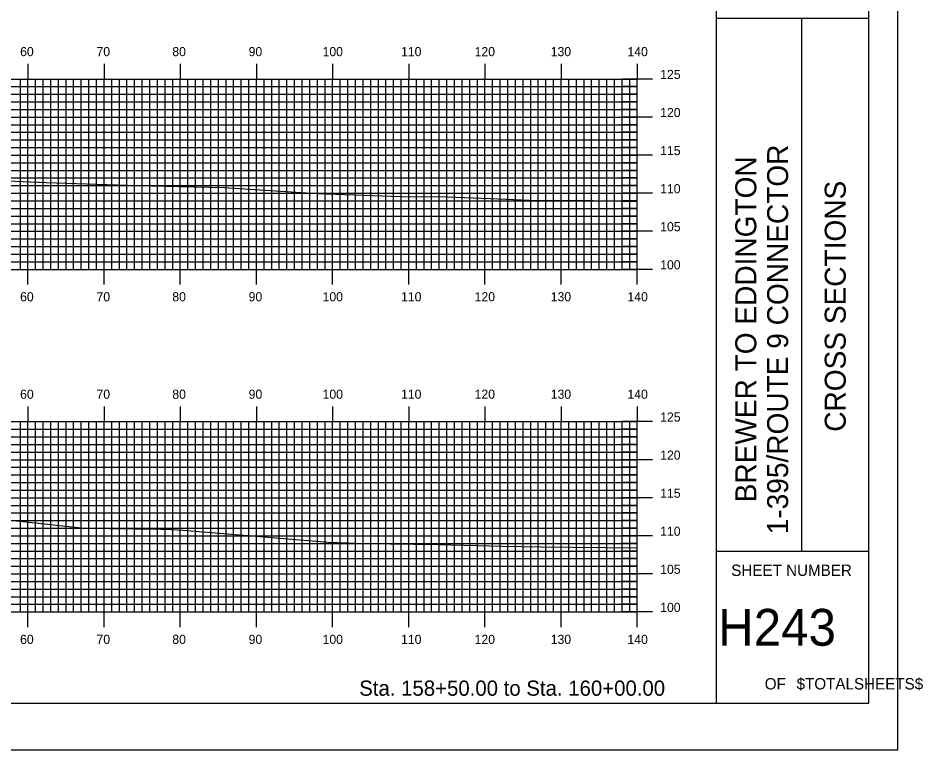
# Model space of a CAD drawing. Extents: x 1779893 to 1780236, y 442591 to 442811.
# Drawn here: x 1780117.1 to 1780235.9, y 442590.5 to 442686.7 of the extents above; entities that cross this region are included whole.
import ezdxf

# ---------------------------------------------------------------- set-up
doc = ezdxf.new("R2010")
doc.units = 0
for name, color, linetype in [('BORDER', 7, 'Continuous'), ('H_V ANNOTATION', 7, 'Continuous'), ('MAJOR', 7, 'Continuous'), ('MINOR', 7, 'Continuous'), ('PLOT BOUNDARY', 7, 'Continuous'), ('S_Roadway_Centerline', 7, 'Continuous')]:
    doc.layers.add(name, color=color, linetype=linetype)

msp = doc.modelspace()

# ---------------------------------------------------------------- linework, layer by layer
at = {"layer": 'BORDER'}
for p, q in [((1780208.76, 442596.67), (1780208.76, 442806.67)), ((1780208.76, 442686.67), (1780228.76, 442686.67)), ((1780219.94, 442616.67), (1780219.94, 442686.67)), ((1780208.76, 442616.67), (1780228.76, 442616.67))]:
    msp.add_line(p, q, dxfattribs=at)
msp.add_lwpolyline([(1779908.76, 442596.67), (1780228.76, 442596.67), (1780228.76, 442806.67), (1779908.76, 442806.67)], close=True, dxfattribs=at)
at = {"layer": 'MAJOR'}
for p, q in [((1780118.36, 442680.67), (1780118.36, 442678.67)), ((1780128.36, 442680.67), (1780128.36, 442678.67)), ((1780138.36, 442680.67), (1780138.36, 442678.67)), ((1780148.36, 442680.67), (1780148.36, 442678.67)), ((1780158.36, 442680.67), (1780158.36, 442678.67)), ((1780168.36, 442680.67), (1780168.36, 442678.67)), ((1780178.36, 442680.67), (1780178.36, 442678.67)), ((1780188.36, 442680.67), (1780188.36, 442678.67)), ((1780198.36, 442680.67), (1780198.36, 442678.67)), ((1779918.36, 442678.67), (1780198.36, 442678.67)), ((1779918.36, 442678.67), (1780198.36, 442678.67)), ((1780118.36, 442653.67), (1780118.36, 442678.67)), ((1780128.36, 442653.67), (1780128.36, 442678.67)), ((1780138.36, 442653.67), (1780138.36, 442678.67)), ((1780148.36, 442653.67), (1780148.36, 442678.67)), ((1780158.36, 442653.67), (1780158.36, 442678.67)), ((1780168.36, 442653.67), (1780168.36, 442678.67)), ((1780178.36, 442653.67), (1780178.36, 442678.67)), ((1780188.36, 442653.67), (1780188.36, 442678.67)), ((1780200.36, 442678.67), (1780196.35, 442678.67)), ((1780198.36, 442653.67), (1780198.36, 442678.67)), ((1780198.36, 442653.67), (1780198.36, 442678.67)), ((1779918.36, 442673.67), (1780198.36, 442673.67)), ((1780200.36, 442673.67), (1780196.35, 442673.67)), ((1779918.36, 442668.67), (1780198.36, 442668.67)), ((1780200.36, 442668.67), (1780196.35, 442668.67)), ((1779918.36, 442663.67), (1780198.36, 442663.67)), ((1780200.36, 442663.67), (1780196.35, 442663.67)), ((1779918.36, 442658.67), (1780198.36, 442658.67)), ((1780200.36, 442658.67), (1780196.35, 442658.67)), ((1779918.36, 442653.67), (1780198.36, 442653.67)), ((1779918.36, 442653.67), (1780198.36, 442653.67)), ((1780118.36, 442651.66), (1780118.36, 442653.67)), ((1780128.36, 442651.66), (1780128.36, 442653.67)), ((1780138.36, 442651.66), (1780138.36, 442653.67)), ((1780148.36, 442651.66), (1780148.36, 442653.67)), ((1780158.36, 442651.66), (1780158.36, 442653.67)), ((1780168.36, 442651.66), (1780168.36, 442653.67)), ((1780178.36, 442651.66), (1780178.36, 442653.67)), ((1780188.36, 442651.66), (1780188.36, 442653.67)), ((1780200.36, 442653.67), (1780196.35, 442653.67)), ((1780198.36, 442651.66), (1780198.36, 442653.67)), ((1780118.36, 442635.67), (1780118.36, 442633.67)), ((1780128.36, 442635.67), (1780128.36, 442633.67)), ((1780138.36, 442635.67), (1780138.36, 442633.67)), ((1780148.36, 442635.67), (1780148.36, 442633.67)), ((1780158.36, 442635.67), (1780158.36, 442633.67)), ((1780168.36, 442635.67), (1780168.36, 442633.67)), ((1780178.36, 442635.67), (1780178.36, 442633.67)), ((1780188.36, 442635.67), (1780188.36, 442633.67)), ((1780198.36, 442635.67), (1780198.36, 442633.67)), ((1779918.36, 442633.67), (1780198.36, 442633.67)), ((1779918.36, 442633.67), (1780198.36, 442633.67)), ((1780118.36, 442608.67), (1780118.36, 442633.67)), ((1780128.36, 442608.67), (1780128.36, 442633.67)), ((1780138.36, 442608.67), (1780138.36, 442633.67)), ((1780148.36, 442608.67), (1780148.36, 442633.67)), ((1780158.36, 442608.67), (1780158.36, 442633.67)), ((1780168.36, 442608.67), (1780168.36, 442633.67)), ((1780178.36, 442608.67), (1780178.36, 442633.67)), ((1780188.36, 442608.67), (1780188.36, 442633.67)), ((1780200.36, 442633.67), (1780196.35, 442633.67)), ((1780198.36, 442608.67), (1780198.36, 442633.67)), ((1780198.36, 442608.67), (1780198.36, 442633.67)), ((1779918.36, 442628.67), (1780198.36, 442628.67)), ((1780200.36, 442628.67), (1780196.35, 442628.67)), ((1779918.36, 442623.67), (1780198.36, 442623.67)), ((1780200.36, 442623.67), (1780196.35, 442623.67)), ((1779918.36, 442618.67), (1780198.36, 442618.67)), ((1780200.36, 442618.67), (1780196.35, 442618.67)), ((1779918.36, 442613.67), (1780198.36, 442613.67)), ((1780200.36, 442613.67), (1780196.35, 442613.67)), ((1779918.36, 442608.67), (1780198.36, 442608.67)), ((1779918.36, 442608.67), (1780198.36, 442608.67)), ((1780118.36, 442606.66), (1780118.36, 442608.67)), ((1780128.36, 442606.66), (1780128.36, 442608.67)), ((1780138.36, 442606.66), (1780138.36, 442608.67)), ((1780148.36, 442606.66), (1780148.36, 442608.67)), ((1780158.36, 442606.66), (1780158.36, 442608.67)), ((1780168.36, 442606.66), (1780168.36, 442608.67)), ((1780178.36, 442606.66), (1780178.36, 442608.67)), ((1780188.36, 442606.66), (1780188.36, 442608.67)), ((1780200.36, 442608.67), (1780196.35, 442608.67)), ((1780198.36, 442606.66), (1780198.36, 442608.67))]:
    msp.add_line(p, q, dxfattribs=at)
at = {"layer": 'MINOR'}
for p, q in [((1779918.36, 442677.67), (1780198.36, 442677.67)), ((1780117.36, 442653.67), (1780117.36, 442678.67)), ((1780119.36, 442653.67), (1780119.36, 442678.67)), ((1780120.36, 442653.67), (1780120.36, 442678.67)), ((1780121.36, 442653.67), (1780121.36, 442678.67)), ((1780122.36, 442653.67), (1780122.36, 442678.67)), ((1780123.36, 442653.67), (1780123.36, 442678.67)), ((1780124.36, 442653.67), (1780124.36, 442678.67)), ((1780125.36, 442653.67), (1780125.36, 442678.67)), ((1780126.36, 442653.67), (1780126.36, 442678.67)), ((1780127.36, 442653.67), (1780127.36, 442678.67)), ((1780129.36, 442653.67), (1780129.36, 442678.67)), ((1780130.36, 442653.67), (1780130.36, 442678.67)), ((1780131.36, 442653.67), (1780131.36, 442678.67)), ((1780132.36, 442653.67), (1780132.36, 442678.67)), ((1780133.36, 442653.67), (1780133.36, 442678.67)), ((1780134.36, 442653.67), (1780134.36, 442678.67)), ((1780135.36, 442653.67), (1780135.36, 442678.67)), ((1780136.36, 442653.67), (1780136.36, 442678.67)), ((1780137.36, 442653.67), (1780137.36, 442678.67)), ((1780139.36, 442653.67), (1780139.36, 442678.67)), ((1780140.36, 442653.67), (1780140.36, 442678.67)), ((1780141.36, 442653.67), (1780141.36, 442678.67)), ((1780142.36, 442653.67), (1780142.36, 442678.67)), ((1780143.36, 442653.67), (1780143.36, 442678.67)), ((1780144.36, 442653.67), (1780144.36, 442678.67)), ((1780145.36, 442653.67), (1780145.36, 442678.67)), ((1780146.36, 442653.67), (1780146.36, 442678.67)), ((1780147.36, 442653.67), (1780147.36, 442678.67)), ((1780149.36, 442653.67), (1780149.36, 442678.67)), ((1780150.36, 442653.67), (1780150.36, 442678.67)), ((1780151.36, 442653.67), (1780151.36, 442678.67)), ((1780152.36, 442653.67), (1780152.36, 442678.67)), ((1780153.36, 442653.67), (1780153.36, 442678.67)), ((1780154.36, 442653.67), (1780154.36, 442678.67)), ((1780155.36, 442653.67), (1780155.36, 442678.67)), ((1780156.36, 442653.67), (1780156.36, 442678.67)), ((1780157.36, 442653.67), (1780157.36, 442678.67)), ((1780159.36, 442653.67), (1780159.36, 442678.67)), ((1780160.36, 442653.67), (1780160.36, 442678.67)), ((1780161.36, 442653.67), (1780161.36, 442678.67)), ((1780162.36, 442653.67), (1780162.36, 442678.67)), ((1780163.36, 442653.67), (1780163.36, 442678.67)), ((1780164.36, 442653.67), (1780164.36, 442678.67)), ((1780165.36, 442653.67), (1780165.36, 442678.67)), ((1780166.36, 442653.67), (1780166.36, 442678.67)), ((1780167.36, 442653.67), (1780167.36, 442678.67)), ((1780169.36, 442653.67), (1780169.36, 442678.67)), ((1780170.36, 442653.67), (1780170.36, 442678.67)), ((1780171.36, 442653.67), (1780171.36, 442678.67)), ((1780172.36, 442653.67), (1780172.36, 442678.67)), ((1780173.36, 442653.67), (1780173.36, 442678.67)), ((1780174.36, 442653.67), (1780174.36, 442678.67)), ((1780175.36, 442653.67), (1780175.36, 442678.67)), ((1780176.36, 442653.67), (1780176.36, 442678.67)), ((1780177.36, 442653.67), (1780177.36, 442678.67)), ((1780179.36, 442653.67), (1780179.36, 442678.67)), ((1780180.36, 442653.67), (1780180.36, 442678.67)), ((1780181.36, 442653.67), (1780181.36, 442678.67)), ((1780182.36, 442653.67), (1780182.36, 442678.67)), ((1780183.36, 442653.67), (1780183.36, 442678.67)), ((1780184.36, 442653.67), (1780184.36, 442678.67)), ((1780185.36, 442653.67), (1780185.36, 442678.67)), ((1780186.36, 442653.67), (1780186.36, 442678.67)), ((1780187.36, 442653.67), (1780187.36, 442678.67)), ((1780189.36, 442653.67), (1780189.36, 442678.67)), ((1780190.36, 442653.67), (1780190.36, 442678.67)), ((1780191.36, 442653.67), (1780191.36, 442678.67)), ((1780192.36, 442653.67), (1780192.36, 442678.67)), ((1780193.36, 442653.67), (1780193.36, 442678.67)), ((1780194.36, 442653.67), (1780194.36, 442678.67)), ((1780195.36, 442653.67), (1780195.36, 442678.67)), ((1780198.36, 442677.67), (1780196.35, 442677.67)), ((1780196.36, 442653.67), (1780196.36, 442678.67)), ((1780197.36, 442653.67), (1780197.36, 442678.67)), ((1779918.36, 442676.67), (1780198.36, 442676.67)), ((1780198.36, 442676.67), (1780196.35, 442676.67)), ((1779918.36, 442675.67), (1780198.36, 442675.67)), ((1780198.36, 442675.67), (1780196.35, 442675.67)), ((1779918.36, 442674.67), (1780198.36, 442674.67)), ((1780198.36, 442674.67), (1780196.35, 442674.67)), ((1779918.36, 442672.67), (1780198.36, 442672.67)), ((1779918.36, 442671.67), (1780198.36, 442671.67)), ((1780198.36, 442672.67), (1780196.35, 442672.67)), ((1780198.36, 442671.67), (1780196.35, 442671.67)), ((1779918.36, 442670.67), (1780198.36, 442670.67)), ((1780198.36, 442670.67), (1780196.35, 442670.67)), ((1779918.36, 442669.67), (1780198.36, 442669.67)), ((1780198.36, 442669.67), (1780196.35, 442669.67)), ((1779918.36, 442667.67), (1780198.36, 442667.67)), ((1780198.36, 442667.67), (1780196.35, 442667.67)), ((1779918.36, 442666.67), (1780198.36, 442666.67)), ((1779918.36, 442665.67), (1780198.36, 442665.67)), ((1780198.36, 442666.67), (1780196.35, 442666.67)), ((1780198.36, 442665.67), (1780196.35, 442665.67)), ((1779918.36, 442664.67), (1780198.36, 442664.67)), ((1780198.36, 442664.67), (1780196.35, 442664.67)), ((1779918.36, 442662.67), (1780198.36, 442662.67)), ((1780198.36, 442662.67), (1780196.35, 442662.67)), ((1779918.36, 442661.67), (1780198.36, 442661.67)), ((1780198.36, 442661.67), (1780196.35, 442661.67)), ((1779918.36, 442660.67), (1780198.36, 442660.67)), ((1780198.36, 442660.67), (1780196.35, 442660.67)), ((1779918.36, 442659.67), (1780198.36, 442659.67)), ((1780198.36, 442659.67), (1780196.35, 442659.67)), ((1779918.36, 442657.67), (1780198.36, 442657.67)), ((1780198.36, 442657.67), (1780196.35, 442657.67)), ((1779918.36, 442656.67), (1780198.36, 442656.67)), ((1780198.36, 442656.67), (1780196.35, 442656.67)), ((1779918.36, 442655.67), (1780198.36, 442655.67)), ((1780198.36, 442655.67), (1780196.35, 442655.67)), ((1779918.36, 442654.67), (1780198.36, 442654.67)), ((1780198.36, 442654.67), (1780196.35, 442654.67)), ((1780117.36, 442608.67), (1780117.36, 442633.67)), ((1780119.36, 442608.67), (1780119.36, 442633.67)), ((1780120.36, 442608.67), (1780120.36, 442633.67)), ((1780121.36, 442608.67), (1780121.36, 442633.67)), ((1780122.36, 442608.67), (1780122.36, 442633.67)), ((1780123.36, 442608.67), (1780123.36, 442633.67)), ((1780124.36, 442608.67), (1780124.36, 442633.67)), ((1780125.36, 442608.67), (1780125.36, 442633.67)), ((1780126.36, 442608.67), (1780126.36, 442633.67)), ((1780127.36, 442608.67), (1780127.36, 442633.67)), ((1780129.36, 442608.67), (1780129.36, 442633.67)), ((1780130.36, 442608.67), (1780130.36, 442633.67)), ((1780131.36, 442608.67), (1780131.36, 442633.67)), ((1780132.36, 442608.67), (1780132.36, 442633.67)), ((1780133.36, 442608.67), (1780133.36, 442633.67)), ((1780134.36, 442608.67), (1780134.36, 442633.67)), ((1780135.36, 442608.67), (1780135.36, 442633.67)), ((1780136.36, 442608.67), (1780136.36, 442633.67)), ((1780137.36, 442608.67), (1780137.36, 442633.67)), ((1780139.36, 442608.67), (1780139.36, 442633.67)), ((1780140.36, 442608.67), (1780140.36, 442633.67)), ((1780141.36, 442608.67), (1780141.36, 442633.67)), ((1780142.36, 442608.67), (1780142.36, 442633.67)), ((1780143.36, 442608.67), (1780143.36, 442633.67)), ((1780144.36, 442608.67), (1780144.36, 442633.67)), ((1780145.36, 442608.67), (1780145.36, 442633.67)), ((1780146.36, 442608.67), (1780146.36, 442633.67)), ((1780147.36, 442608.67), (1780147.36, 442633.67)), ((1780149.36, 442608.67), (1780149.36, 442633.67)), ((1780150.36, 442608.67), (1780150.36, 442633.67)), ((1780151.36, 442608.67), (1780151.36, 442633.67)), ((1780152.36, 442608.67), (1780152.36, 442633.67)), ((1780153.36, 442608.67), (1780153.36, 442633.67)), ((1780154.36, 442608.67), (1780154.36, 442633.67)), ((1780155.36, 442608.67), (1780155.36, 442633.67)), ((1780156.36, 442608.67), (1780156.36, 442633.67)), ((1780157.36, 442608.67), (1780157.36, 442633.67)), ((1780159.36, 442608.67), (1780159.36, 442633.67)), ((1780160.36, 442608.67), (1780160.36, 442633.67)), ((1780161.36, 442608.67), (1780161.36, 442633.67)), ((1780162.36, 442608.67), (1780162.36, 442633.67)), ((1780163.36, 442608.67), (1780163.36, 442633.67)), ((1780164.36, 442608.67), (1780164.36, 442633.67)), ((1780165.36, 442608.67), (1780165.36, 442633.67)), ((1780166.36, 442608.67), (1780166.36, 442633.67)), ((1780167.36, 442608.67), (1780167.36, 442633.67)), ((1780169.36, 442608.67), (1780169.36, 442633.67)), ((1780170.36, 442608.67), (1780170.36, 442633.67)), ((1780171.36, 442608.67), (1780171.36, 442633.67)), ((1780172.36, 442608.67), (1780172.36, 442633.67)), ((1780173.36, 442608.67), (1780173.36, 442633.67)), ((1780174.36, 442608.67), (1780174.36, 442633.67)), ((1780175.36, 442608.67), (1780175.36, 442633.67)), ((1780176.36, 442608.67), (1780176.36, 442633.67)), ((1780177.36, 442608.67), (1780177.36, 442633.67)), ((1780179.36, 442608.67), (1780179.36, 442633.67)), ((1780180.36, 442608.67), (1780180.36, 442633.67)), ((1780181.36, 442608.67), (1780181.36, 442633.67)), ((1780182.36, 442608.67), (1780182.36, 442633.67)), ((1780183.36, 442608.67), (1780183.36, 442633.67)), ((1780184.36, 442608.67), (1780184.36, 442633.67)), ((1780185.36, 442608.67), (1780185.36, 442633.67)), ((1780186.36, 442608.67), (1780186.36, 442633.67)), ((1780187.36, 442608.67), (1780187.36, 442633.67)), ((1780189.36, 442608.67), (1780189.36, 442633.67)), ((1780190.36, 442608.67), (1780190.36, 442633.67)), ((1780191.36, 442608.67), (1780191.36, 442633.67)), ((1780192.36, 442608.67), (1780192.36, 442633.67)), ((1780193.36, 442608.67), (1780193.36, 442633.67)), ((1780194.36, 442608.67), (1780194.36, 442633.67)), ((1780195.36, 442608.67), (1780195.36, 442633.67)), ((1780196.36, 442608.67), (1780196.36, 442633.67)), ((1780197.36, 442608.67), (1780197.36, 442633.67)), ((1779918.36, 442632.67), (1780198.36, 442632.67)), ((1780198.36, 442632.67), (1780196.35, 442632.67)), ((1779918.36, 442631.67), (1780198.36, 442631.67)), ((1780198.36, 442631.67), (1780196.35, 442631.67)), ((1779918.36, 442630.67), (1780198.36, 442630.67)), ((1780198.36, 442630.67), (1780196.35, 442630.67)), ((1779918.36, 442629.67), (1780198.36, 442629.67)), ((1780198.36, 442629.67), (1780196.35, 442629.67)), ((1779918.36, 442627.67), (1780198.36, 442627.67)), ((1780198.36, 442627.67), (1780196.35, 442627.67)), ((1779918.36, 442626.67), (1780198.36, 442626.67)), ((1780198.36, 442626.67), (1780196.35, 442626.67)), ((1779918.36, 442625.67), (1780198.36, 442625.67)), ((1780198.36, 442625.67), (1780196.35, 442625.67)), ((1779918.36, 442624.67), (1780198.36, 442624.67)), ((1780198.36, 442624.67), (1780196.35, 442624.67)), ((1779918.36, 442622.67), (1780198.36, 442622.67)), ((1780198.36, 442622.67), (1780196.35, 442622.67)), ((1779918.36, 442621.67), (1780198.36, 442621.67)), ((1779918.36, 442620.67), (1780198.36, 442620.67)), ((1780198.36, 442621.67), (1780196.35, 442621.67)), ((1780198.36, 442620.67), (1780196.35, 442620.67)), ((1779918.36, 442619.67), (1780198.36, 442619.67)), ((1780198.36, 442619.67), (1780196.35, 442619.67)), ((1779918.36, 442617.67), (1780198.36, 442617.67)), ((1780198.36, 442617.67), (1780196.35, 442617.67)), ((1779918.36, 442616.67), (1780198.36, 442616.67)), ((1780198.36, 442616.67), (1780196.35, 442616.67)), ((1779918.36, 442615.67), (1780198.36, 442615.67)), ((1779918.36, 442614.67), (1780198.36, 442614.67)), ((1780198.36, 442615.67), (1780196.35, 442615.67)), ((1780198.36, 442614.67), (1780196.35, 442614.67)), ((1779918.36, 442612.67), (1780198.36, 442612.67)), ((1780198.36, 442612.67), (1780196.35, 442612.67)), ((1779918.36, 442611.67), (1780198.36, 442611.67)), ((1780198.36, 442611.67), (1780196.35, 442611.67)), ((1779918.36, 442610.67), (1780198.36, 442610.67)), ((1780198.36, 442610.67), (1780196.35, 442610.67)), ((1779918.36, 442609.67), (1780198.36, 442609.67)), ((1780198.36, 442609.67), (1780196.35, 442609.67))]:
    msp.add_line(p, q, dxfattribs=at)
at = {"layer": 'PLOT BOUNDARY'}
msp.add_lwpolyline([(1779892.57, 442590.55), (1780232.57, 442590.55), (1780232.57, 442810.55), (1779892.57, 442810.55)], close=True, dxfattribs=at)
at = {"layer": 'S_Roadway_Centerline'}
for points in [[(1780115.63, 442665.3), (1780120.75, 442665.09), (1780132.74, 442664.68), (1780138.2, 442664.54), (1780144.12, 442664.42), (1780156.27, 442663.64), (1780167.29, 442663.24), (1780173.45, 442663.21), (1780179.05, 442662.98), (1780185.15, 442662.71), (1780192.55, 442662.7), (1780198.36, 442662.6)], [(1780114.01, 442620.96), (1780125.74, 442619.66), (1780135.78, 442619.56), (1780137.14, 442619.52), (1780138.72, 442619.42), (1780157.79, 442617.83), (1780162.67, 442617.65), (1780172.23, 442617.52), (1780180.6, 442617.29), (1780185.73, 442617.22), (1780198.36, 442617.11)]]:
    msp.add_lwpolyline(points, dxfattribs=at)

# ---------------------------------------------------------------- texts
at = {"layer": 'BORDER'}
for s, p in [('1-395/ROUTE 9 CONNECTOR', (1780218.16, 442618.87)), ('BREWER TO EDDINGTON', (1780213.98, 442623.07)), ('CROSS SECTIONS', (1780225.72, 442632.34))]:
    msp.add_text(s, height=2.7557, rotation=90, dxfattribs=at).set_placement(p)
for s, height, p in [('SHEET NUMBER', 1.4905, (1780210.69, 442613.4)), ('H243', 4.839, (1780208.97, 442604.23)), ('OF', 1.491, (1780215.09, 442598.49)), ('$TOTALSHEETS$', 1.4905, (1780219.27, 442598.49))]:
    msp.add_text(s, height=height, dxfattribs=at).set_placement(p)
at = {"layer": 'H_V ANNOTATION'}
for s, height, p in [('60', 1.2, (1780117.33, 442681.67)), ('70', 1.2, (1780127.36, 442681.67)), ('80', 1.2, (1780137.31, 442681.67)), ('90', 1.2, (1780147.33, 442681.67)), ('100', 1.2, (1780157.04, 442681.67)), ('110', 1.2, (1780167.34, 442681.67)), ('120', 1.2, (1780177, 442681.67)), ('130', 1.2, (1780186.99, 442681.67)), ('140', 1.2, (1780197.06, 442681.67)), ('125', 1.2, (1780201.36, 442678.67)), ('120', 1.2, (1780201.36, 442673.67)), ('115', 1.2, (1780201.36, 442668.67)), ('110', 1.2, (1780201.36, 442663.67)), ('105', 1.2, (1780201.36, 442658.67)), ('100', 1.2, (1780201.36, 442653.67)), ('60', 1.2, (1780117.33, 442649.47)), ('70', 1.2, (1780127.36, 442649.47)), ('80', 1.2, (1780137.31, 442649.47)), ('90', 1.2, (1780147.33, 442649.47)), ('100', 1.2, (1780157.04, 442649.47)), ('110', 1.2, (1780167.34, 442649.47)), ('120', 1.2, (1780177, 442649.47)), ('130', 1.2, (1780186.99, 442649.47)), ('140', 1.2, (1780197.06, 442649.47)), ('60', 1.2, (1780117.33, 442636.67)), ('70', 1.2, (1780127.36, 442636.67)), ('80', 1.2, (1780137.31, 442636.67)), ('90', 1.2, (1780147.33, 442636.67)), ('100', 1.2, (1780157.04, 442636.67)), ('110', 1.2, (1780167.34, 442636.67)), ('120', 1.2, (1780177, 442636.67)), ('130', 1.2, (1780186.99, 442636.67)), ('140', 1.2, (1780197.06, 442636.67)), ('125', 1.2, (1780201.36, 442633.67)), ('120', 1.2, (1780201.36, 442628.67)), ('115', 1.2, (1780201.36, 442623.67)), ('110', 1.2, (1780201.36, 442618.67)), ('105', 1.2, (1780201.36, 442613.67)), ('100', 1.2, (1780201.36, 442608.67)), ('60', 1.2, (1780117.33, 442604.47)), ('70', 1.2, (1780127.36, 442604.47)), ('80', 1.2, (1780137.31, 442604.47)), ('90', 1.2, (1780147.33, 442604.47)), ('100', 1.2, (1780157.04, 442604.47)), ('110', 1.2, (1780167.34, 442604.47)), ('120', 1.2, (1780177, 442604.47)), ('130', 1.2, (1780186.99, 442604.47)), ('140', 1.2, (1780197.06, 442604.47)), ('Sta. 158+50.00 to Sta. 160+00.00', 2.0004, (1780161.85, 442597.66))]:
    msp.add_text(s, height=height, dxfattribs=at).set_placement(p)

doc.saveas('drawing.dxf')
